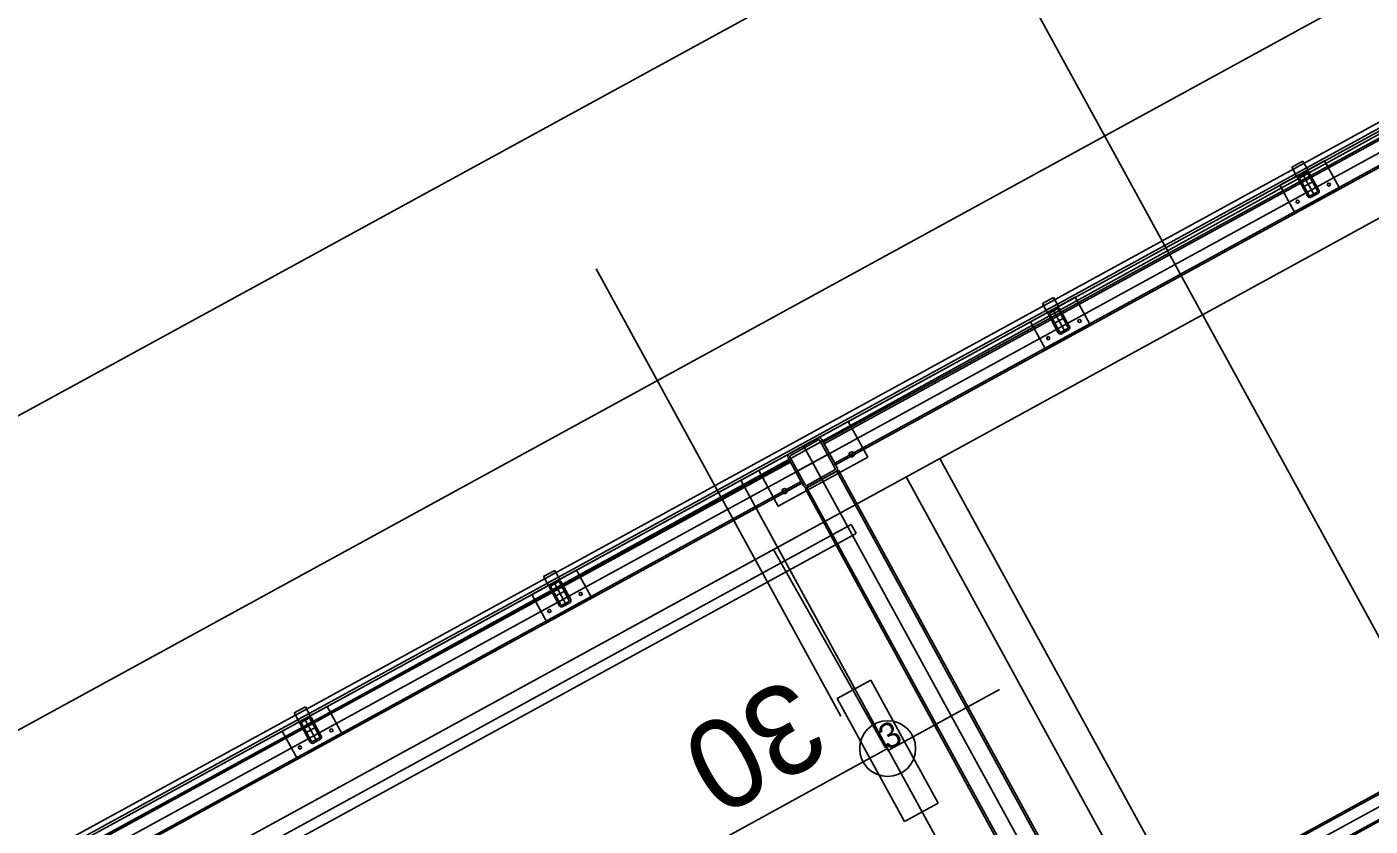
# Model space of a CAD drawing. Extents: x -783978 to -783565, y -1064821 to -1064596.
# Drawn here: x -783741.25 to -783735.98, y -1064667.56 to -1064664.43 of the extents above; entities that cross this region are included whole.
import ezdxf

# ---------------------------------------------------------------- set-up
doc = ezdxf.new("R2010")
doc.units = 0
for name, color, linetype in [('Default', 7, 'Continuous'), ('SO 01_11_01', 7, 'Continuous'), ('SO 01_20_01', 7, 'Continuous'), ('SO 01_50_01', 7, 'Continuous'), ('SO 01_74_01', 7, 'Continuous'), ('SO 01_86_04', 7, 'Continuous')]:
    doc.layers.add(name, color=color, linetype=linetype)

# ---------------------------------------------------------------- blocks, each defined once
blk = doc.blocks.new('POINT_DISPLAY')
at = {"layer": 'Default'}
blk.add_line((0, 0), (0, 0), dxfattribs=at)

msp = doc.modelspace()

# ---------------------------------------------------------------- linework, layer by layer
at = {"layer": 'SO 01_11_01'}
msp.add_line((-783772.8819, -1064683.2217), (-783730.898, -1064660.279), dxfattribs=at)
at = {"layer": 'SO 01_20_01'}
for p, q in [((-783726.9264, -1064683.3119), (-783738.1468, -1064662.8034)), ((-783735.0054, -1064663.7532), (-783787.4671, -1064692.4555)), ((-783735.2041, -1064664.4318), (-783786.7885, -1064692.6541)), ((-783786.6445, -1064692.9173), (-783735.3233, -1064664.839)), ((-783735.7981, -1064669.5443), (-783737.67, -1064666.1229)), ((-783737.4421, -1064668.05), (-783738.45, -1064666.2077)), ((-783735.9297, -1064669.6163), (-783737.8016, -1064666.1949)), ((-783738.0171, -1064666.3812), (-783786.4402, -1064692.874)), ((-783738.0171, -1064666.3812), (-783737.9981, -1064666.416)), ((-783786.421, -1064692.9091), (-783737.9979, -1064666.4163)), ((-783737.4421, -1064668.05), (-783738.3061, -1064666.4709)), ((-783737.8741, -1064667.2605), (-783785.3352, -1064693.2269))]:
    msp.add_line(p, q, dxfattribs=at)
msp.add_circle((-783737.8741, -1064667.2605), 0.1095, dxfattribs=at)
at = {"layer": 'SO 01_50_01'}
for p, q in [((-783786.7885, -1064692.6541), (-783725.4827, -1064659.1131)), ((-783738.5378, -1064666.2557), (-783734.1523, -1064663.8564)), ((-783738.5378, -1064666.2558), (-783734.1522, -1064663.8565)), ((-783738.5378, -1064666.2558), (-783734.1522, -1064663.8565)), ((-783738.0579, -1064667.133), (-783739.0178, -1064665.3785)), ((-783742.9243, -1064668.6556), (-783738.5378, -1064666.2557)), ((-783742.9242, -1064668.6557), (-783738.5378, -1064666.2558)), ((-783742.9242, -1064668.6557), (-783738.5378, -1064666.2558))]:
    msp.add_line(p, q, dxfattribs=at)
at = {"layer": 'SO 01_74_01'}
for p, q in [((-783735.2185, -1064664.4055), (-783786.6099, -1064692.5222)), ((-783786.6003, -1064692.5398), (-783735.2089, -1064664.423)), ((-783735.3237, -1064664.5257), (-783738.1265, -1064666.0592)), ((-783735.3207, -1064664.5313), (-783738.1235, -1064666.0647)), ((-783738.0815, -1064666.1414), (-783735.2787, -1064664.608)), ((-783738.0785, -1064666.1469), (-783735.2757, -1064664.6135)), ((-783736.2453, -1064664.9559), (-783736.2892, -1064664.9799)), ((-783736.2892, -1064664.9799), (-783736.27, -1064665.015)), ((-783736.2405, -1064664.9647), (-783736.2844, -1064664.9887)), ((-783736.2261, -1064664.991), (-783736.2453, -1064664.9559)), ((-783736.2309, -1064664.9822), (-783736.2405, -1064664.9647)), ((-783736.2844, -1064664.9887), (-783736.2748, -1064665.0062)), ((-783736.2748, -1064665.0062), (-783736.2309, -1064664.9822)), ((-783736.27, -1064665.015), (-783736.2261, -1064664.991)), ((-783737.2235, -1064665.4911), (-783737.2674, -1064665.5151)), ((-783737.2187, -1064665.4998), (-783737.2626, -1064665.5238)), ((-783737.2043, -1064665.5262), (-783737.2235, -1064665.4911)), ((-783737.2091, -1064665.5174), (-783737.2187, -1064665.4998)), ((-783737.2674, -1064665.5151), (-783737.2482, -1064665.5502)), ((-783737.2626, -1064665.5238), (-783737.253, -1064665.5414)), ((-783737.253, -1064665.5414), (-783737.2091, -1064665.5174)), ((-783737.2482, -1064665.5502), (-783737.2043, -1064665.5262)), ((-783738.1265, -1064666.0592), (-783738.0785, -1064666.1469)), ((-783738.1235, -1064666.0647), (-783738.0815, -1064666.1414)), ((-783738.2582, -1064666.1313), (-783741.061, -1064667.6647)), ((-783738.2552, -1064666.1368), (-783741.058, -1064667.6702)), ((-783738.2102, -1064666.219), (-783738.2582, -1064666.1313)), ((-783738.2132, -1064666.2135), (-783738.2552, -1064666.1368)), ((-783738.1982, -1064666.2409), (-783738.0666, -1064666.1689)), ((-783738.1912, -1064666.2371), (-783738.0736, -1064666.1728)), ((-783738.0736, -1064666.1728), (-783736.0578, -1064669.8574)), ((-783738.0666, -1064666.1689), (-783736.0507, -1064669.8535)), ((-783741.016, -1064667.7469), (-783738.2132, -1064666.2135)), ((-783741.013, -1064667.7524), (-783738.2102, -1064666.219)), ((-783736.1823, -1064669.9255), (-783738.1982, -1064666.2409)), ((-783736.1753, -1064669.9217), (-783738.1912, -1064666.2371)), ((-783734.2438, -1064666.4996), (-783737.0465, -1064668.0331)), ((-783734.2407, -1064666.5052), (-783737.0435, -1064668.0386)), ((-783739.1798, -1064666.5614), (-783739.2237, -1064666.5854)), ((-783739.2237, -1064666.5854), (-783739.2045, -1064666.6205)), ((-783739.175, -1064666.5702), (-783739.2189, -1064666.5942)), ((-783739.2189, -1064666.5942), (-783739.2093, -1064666.6117)), ((-783739.2093, -1064666.6117), (-783739.1654, -1064666.5877)), ((-783739.2045, -1064666.6205), (-783739.1606, -1064666.5965)), ((-783739.1606, -1064666.5965), (-783739.1798, -1064666.5614)), ((-783739.1654, -1064666.5877), (-783739.175, -1064666.5702)), ((-783737.0016, -1064668.1153), (-783734.1988, -1064666.5818)), ((-783736.9985, -1064668.1208), (-783734.1958, -1064666.5874)), ((-783740.158, -1064667.0966), (-783740.2019, -1064667.1206)), ((-783740.2019, -1064667.1206), (-783740.1827, -1064667.1557)), ((-783740.1532, -1064667.1053), (-783740.1971, -1064667.1293)), ((-783740.1971, -1064667.1293), (-783740.1875, -1064667.1469)), ((-783740.1875, -1064667.1469), (-783740.1436, -1064667.1229)), ((-783740.1827, -1064667.1557), (-783740.1388, -1064667.1317)), ((-783740.1388, -1064667.1317), (-783740.158, -1064667.0966)), ((-783740.1436, -1064667.1229), (-783740.1532, -1064667.1053))]:
    msp.add_line(p, q, dxfattribs=at)
for points in [[(-783735.1681, -1064664.4976), (-783787.4762, -1064693.1159)], [(-783736.2655, -1064665.0233), (-783736.2265, -1064665.0944)], [(-783736.2344, -1064664.9955), (-783736.2617, -1064665.0105)], [(-783736.2599, -1064665.0203), (-783736.221, -1064665.0914)], [(-783736.2314, -1064665.001), (-783736.2587, -1064665.016)], [(-783736.2481, -1064665.003), (-783736.2001, -1064665.0907)], [(-783736.1882, -1064665.0734), (-783736.2271, -1064665.0023)], [(-783736.1827, -1064665.0704), (-783736.2216, -1064664.9993)], [(-783736.2021, -1064665.0349), (-783736.246, -1064665.0589)], [(-783736.2167, -1064665.0927), (-783736.1894, -1064665.0777)], [(-783736.2137, -1064665.0982), (-783736.1864, -1064665.0833)], [(-783737.2436, -1064665.5584), (-783737.2047, -1064665.6296)], [(-783737.2126, -1064665.5307), (-783737.2399, -1064665.5456)], [(-783737.2381, -1064665.5554), (-783737.1992, -1064665.6266)], [(-783737.2096, -1064665.5362), (-783737.2369, -1064665.5511)], [(-783737.2262, -1064665.5382), (-783737.1782, -1064665.6259)], [(-783737.1664, -1064665.6086), (-783737.2053, -1064665.5375)], [(-783737.1608, -1064665.6056), (-783737.1998, -1064665.5344)], [(-783737.1803, -1064665.57), (-783737.2242, -1064665.594)], [(-783737.1949, -1064665.6278), (-783737.1676, -1064665.6129)], [(-783737.1919, -1064665.6333), (-783737.1646, -1064665.6184)], [(-783738.1491, -1064666.0431), (-783738.2597, -1064666.1036)], [(-783738.1453, -1064666.0501), (-783738.2558, -1064666.1106)], [(-783738.2044, -1064666.0733), (-783736.0445, -1064670.0211)], [(-783738.1324, -1064666.2049), (-783738.2044, -1064666.0733)], [(-783738.0794, -1064666.1622), (-783738.1399, -1064666.0517)], [(-783738.0724, -1064666.1584), (-783738.1329, -1064666.0479)], [(-783738.2644, -1064666.1198), (-783738.204, -1064666.2304)], [(-783738.2574, -1064666.116), (-783738.197, -1064666.2265)], [(-783738.1026, -1064666.1031), (-783738.2342, -1064666.1751)], [(-783738.1915, -1064666.2281), (-783738.081, -1064666.1677)], [(-783738.1877, -1064666.2352), (-783738.0771, -1064666.1747)], [(-783734.0882, -1064666.4715), (-783786.3963, -1064695.0898)], [(-783739.1689, -1064666.601), (-783739.1962, -1064666.616)], [(-783739.1659, -1064666.6066), (-783739.1932, -1064666.6215)], [(-783739.1826, -1064666.6085), (-783739.1346, -1064666.6962)], [(-783739.1227, -1064666.679), (-783739.1616, -1064666.6078)], [(-783739.1172, -1064666.6759), (-783739.1561, -1064666.6048)], [(-783739.2, -1064666.6288), (-783739.1611, -1064666.6999)], [(-783739.1945, -1064666.6258), (-783739.1555, -1064666.6969)], [(-783739.1367, -1064666.6404), (-783739.1805, -1064666.6644)], [(-783739.1512, -1064666.6982), (-783739.124, -1064666.6832)], [(-783739.1482, -1064666.7037), (-783739.1209, -1064666.6888)], [(-783740.1471, -1064667.1362), (-783740.1744, -1064667.1511)], [(-783740.0954, -1064667.2111), (-783740.1343, -1064667.1399)], [(-783740.1782, -1064667.1639), (-783740.1392, -1064667.2351)], [(-783740.1726, -1064667.1609), (-783740.1337, -1064667.2321)], [(-783740.1441, -1064667.1417), (-783740.1714, -1064667.1566)], [(-783740.1608, -1064667.1437), (-783740.1128, -1064667.2314)], [(-783740.1148, -1064667.1755), (-783740.1587, -1064667.1995)], [(-783740.1009, -1064667.2141), (-783740.1398, -1064667.143)], [(-783740.1294, -1064667.2333), (-783740.1021, -1064667.2184)], [(-783740.1264, -1064667.2388), (-783740.0991, -1064667.2239)]]:
    msp.add_lwpolyline(points, dxfattribs=at)
for points in [[(-783736.1603, -1064664.955), (-783736.3358, -1064665.051), (-783736.2782, -1064665.1563), (-783736.1027, -1064665.0603)], [(-783737.1385, -1064665.4902), (-783737.314, -1064665.5862), (-783737.2564, -1064665.6914), (-783737.0809, -1064665.5954)], [(-783737.9522, -1064666.1177), (-783738.3031, -1064666.3097), (-783738.3799, -1064666.1693), (-783738.029, -1064665.9773)], [(-783739.0949, -1064666.5605), (-783739.2703, -1064666.6565), (-783739.2127, -1064666.7618), (-783739.0373, -1064666.6658)], [(-783740.073, -1064667.0957), (-783740.2485, -1064667.1917), (-783740.1909, -1064667.2969), (-783740.0154, -1064667.2009)]]:
    msp.add_lwpolyline(points, close=True, dxfattribs=at)
for centre, radius in [((-783736.1435, -1064665.0483), 0.006), ((-783736.2663, -1064665.1155), 0.006), ((-783737.1216, -1064665.5835), 0.006), ((-783737.2444, -1064665.6507), 0.006), ((-783738.0152, -1064666.1066), 0.01), ((-783738.2784, -1064666.2506), 0.01), ((-783739.078, -1064666.6538), 0.006), ((-783739.2008, -1064666.721), 0.006), ((-783740.0561, -1064667.189), 0.006), ((-783740.179, -1064667.2562), 0.006)]:
    msp.add_circle(centre, radius, dxfattribs=at)
for centre, radius, start, end in [((-783736.2572, -1064665.0187), 0.00945, 118.6835, 208.6835), ((-783736.2572, -1064665.0187), 0.00315, 118.6835, 208.6835), ((-783736.2299, -1064665.0038), 0.00945, 28.6835, 118.6835), ((-783736.2299, -1064665.0038), 0.00315, 28.6835, 118.6835), ((-783736.191, -1064665.075), 0.00315, 298.6835, 28.6835), ((-783736.191, -1064665.075), 0.00945, 298.6835, 28.6835), ((-783736.2182, -1064665.0899), 0.00945, 208.6835, 298.6835), ((-783736.2182, -1064665.0899), 0.00315, 208.6835, 298.6835), ((-783737.2353, -1064665.5539), 0.00945, 118.6835, 208.6835), ((-783737.2353, -1064665.5539), 0.00315, 118.6835, 208.6835), ((-783737.2081, -1064665.539), 0.00945, 28.6835, 118.6835), ((-783737.2081, -1064665.539), 0.00315, 28.6835, 118.6835), ((-783737.1691, -1064665.6101), 0.00315, 298.6835, 28.6835), ((-783737.1691, -1064665.6101), 0.00945, 298.6835, 28.6835), ((-783737.1964, -1064665.6251), 0.00945, 208.6835, 298.6835), ((-783737.1964, -1064665.6251), 0.00315, 208.6835, 298.6835), ((-783738.1434, -1064666.0536), 0.012, 28.6835, 118.6835), ((-783738.1434, -1064666.0536), 0.004, 28.6835, 118.6835), ((-783738.2539, -1064666.1141), 0.012, 118.6835, 208.6835), ((-783738.2539, -1064666.1141), 0.004, 118.6835, 208.6835), ((-783738.0829, -1064666.1641), 0.004, 298.6835, 28.6835), ((-783738.0829, -1064666.1641), 0.012, 298.6835, 28.6835), ((-783738.1934, -1064666.2246), 0.012, 208.6835, 298.6835), ((-783738.1934, -1064666.2246), 0.004, 208.6835, 298.6835), ((-783739.1644, -1064666.6093), 0.00945, 28.6835, 118.6835), ((-783739.1644, -1064666.6093), 0.00315, 28.6835, 118.6835), ((-783739.1917, -1064666.6242), 0.00945, 118.6835, 208.6835), ((-783739.1917, -1064666.6242), 0.00315, 118.6835, 208.6835), ((-783739.1528, -1064666.6954), 0.00945, 208.6835, 298.6835), ((-783739.1528, -1064666.6954), 0.00315, 208.6835, 298.6835), ((-783739.1255, -1064666.6805), 0.00315, 298.6835, 28.6835), ((-783739.1255, -1064666.6805), 0.00945, 298.6835, 28.6835), ((-783740.1426, -1064667.1445), 0.00945, 28.6835, 118.6835), ((-783740.1699, -1064667.1594), 0.00945, 118.6835, 208.6835), ((-783740.1699, -1064667.1594), 0.00315, 118.6835, 208.6835), ((-783740.1426, -1064667.1445), 0.00315, 28.6835, 118.6835), ((-783740.1309, -1064667.2306), 0.00945, 208.6835, 298.6835), ((-783740.1309, -1064667.2306), 0.00315, 208.6835, 298.6835), ((-783740.1037, -1064667.2156), 0.00315, 298.6835, 28.6835), ((-783740.1037, -1064667.2156), 0.00945, 298.6835, 28.6835)]:
    msp.add_arc(centre, radius, start, end, dxfattribs=at)
at = {"layer": 'SO 01_86_04'}
for p, q in [((-783738.3222, -1064666.4797), (-783737.883, -1064667.2574)), ((-783737.9404, -1064666.9919), (-783738.072, -1064667.0639)), ((-783737.9404, -1064666.9919), (-783738.072, -1064667.0639)), ((-783738.072, -1064667.0639), (-783737.9404, -1064666.9919)), ((-783738.072, -1064667.0639), (-783737.9404, -1064666.9919)), ((-783737.6765, -1064667.4744), (-783737.9404, -1064666.9919)), ((-783737.6765, -1064667.4744), (-783737.9404, -1064666.9919)), ((-783737.9404, -1064666.9919), (-783737.6765, -1064667.4744)), ((-783737.9404, -1064666.9919), (-783737.6765, -1064667.4744)), ((-783737.8743, -1064667.2692), (-783737.4356, -1064667.0292)), ((-783738.072, -1064667.0639), (-783737.8081, -1064667.5464)), ((-783738.072, -1064667.0639), (-783737.8081, -1064667.5464)), ((-783737.8081, -1064667.5464), (-783738.072, -1064667.0639)), ((-783737.8081, -1064667.5464), (-783738.072, -1064667.0639)), ((-783737.8081, -1064667.5464), (-783737.6765, -1064667.4744)), ((-783737.8081, -1064667.5464), (-783737.6765, -1064667.4744)), ((-783737.6765, -1064667.4744), (-783737.8081, -1064667.5464)), ((-783737.6765, -1064667.4744), (-783737.8081, -1064667.5464))]:
    msp.add_line(p, q, dxfattribs=at)
for points in [[(-783735.4626, -1064664.5844), (-783749.7616, -1064672.4637), (-783749.643, -1064672.6735)], [(-783738.3222, -1064666.4797), (-783740.5325, -1064667.689), (-783743.1715, -1064669.1328), (-783745.7538, -1064670.5456), (-783748.4385, -1064672.0145), (-783751.0413, -1064673.4385), (-783753.6847, -1064674.8847), (-783756.3281, -1064676.3309), (-783758.9715, -1064677.7772), (-783761.6149, -1064679.2234), (-783764.2583, -1064680.6696), (-783766.9018, -1064682.1159), (-783769.4633, -1064683.5173), (-783772.109, -1064684.9648), (-783774.7882, -1064686.4306), (-783778.1382, -1064688.2722), (-783783.8139, -1064691.3971), (-783785.747, -1064692.4898)]]:
    msp.add_lwpolyline(points, dxfattribs=at)

# ---------------------------------------------------------------- block references
at = {"layer": 'SO 01_86_04', "xscale": 0.010000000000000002, "yscale": 0.009999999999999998, "rotation": 28.683491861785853}
for p in [(-783737.9404, -1064666.9919), (-783737.9404, -1064666.9919), (-783738.072, -1064667.0639), (-783738.072, -1064667.0639), (-783737.6765, -1064667.4744), (-783737.6765, -1064667.4744), (-783737.8081, -1064667.5464), (-783737.8081, -1064667.5464)]:
    msp.add_blockref('POINT_DISPLAY', p, dxfattribs=at)

# ---------------------------------------------------------------- texts
at = {"layer": 'SO 01_86_04'}
for s, height, rotation, p in [('30', 0.351, 209.46, (-783738.2531, -1064666.9711)), ('3', 0.1, 28.6835, (-783737.8743, -1064667.2692))]:
    msp.add_text(s, height=height, rotation=rotation, dxfattribs=at).set_placement(p)

doc.saveas('drawing.dxf')
